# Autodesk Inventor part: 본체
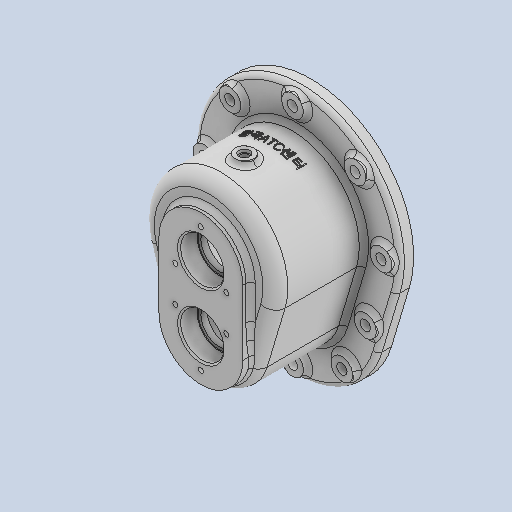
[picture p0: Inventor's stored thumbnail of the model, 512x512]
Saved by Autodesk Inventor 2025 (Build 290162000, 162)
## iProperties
Created: 2026-07
Part Number: 본체
Material: 일반
Document SubType Name: Modeling
Designer: KDI
Density: 1 g/cm^3
Appearance: 기본값
Author: jhkim
Sending System: Autodesk Inventor 2027
Preprocessor: ST-DEVELOPER v20.1
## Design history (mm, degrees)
feature "솔리드1"
node "솔리드2"
